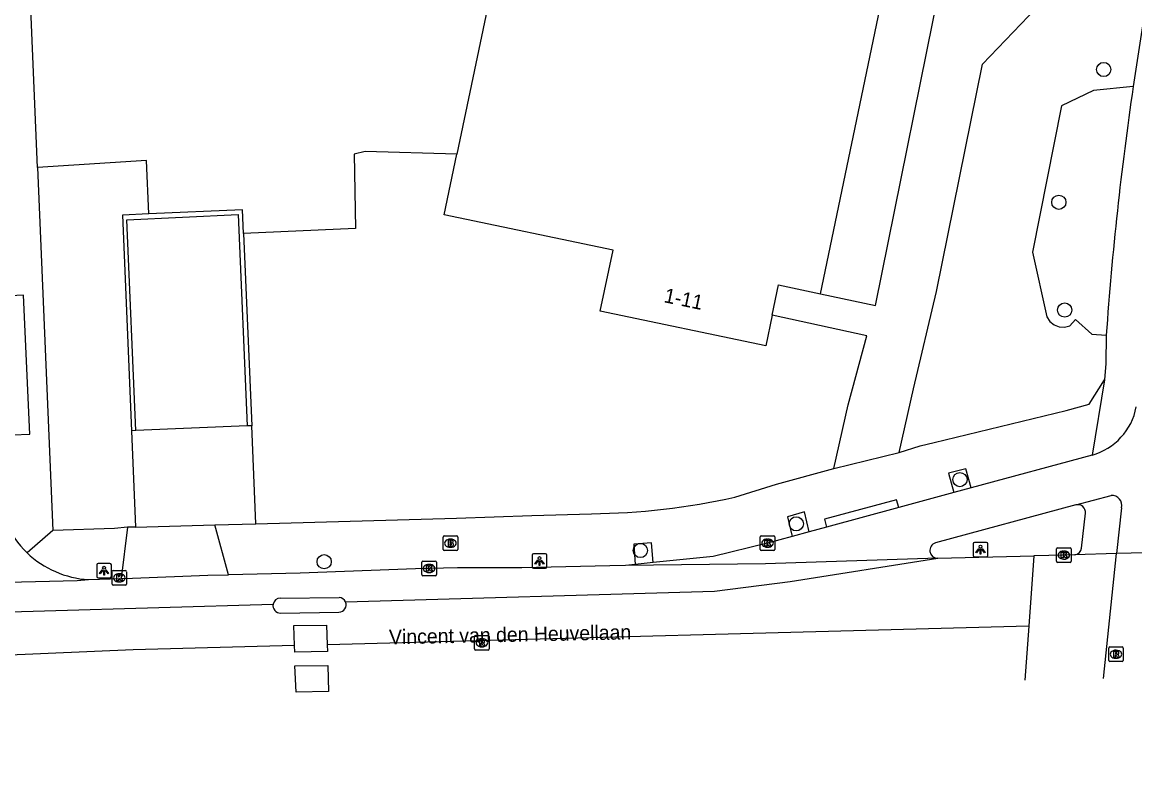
# Model space of a CAD drawing. Extents: x 161243 to 161752, y 384138 to 384885.
# Drawn here: x 161384.5 to 161461, y 384140.9 to 384193.1 of the extents above; entities that cross this region are included whole.
import ezdxf

# ---------------------------------------------------------------- set-up
doc = ezdxf.new("R2010")
doc.units = 0
for name, color, linetype in [('IMGEO_Boom', 7, 'Continuous'), ('IMGEO_Brandkraan', 7, 'Continuous'), ('IMGEO_Fietspad_gesloten', 7, 'Continuous'), ('IMGEO_Groenvoorziening', 7, 'Continuous'), ('IMGEO_Kolk', 7, 'Continuous'), ('IMGEO_Lichtpunt', 7, 'Continuous'), ('IMGEO_Muur', 7, 'Continuous'), ('IMGEO_Openbare_ruimte_label', 7, 'Continuous'), ('IMGEO_Pand', 7, 'Continuous'), ('IMGEO_Pand_nummerreeks', 7, 'Continuous'), ('IMGEO_Rijbaan_lokaal_gesloten', 7, 'Continuous'), ('IMGEO_Rijbaan_lokaal_open', 7, 'Continuous'), ('IMGEO_Rioolput', 7, 'Continuous'), ('IMGEO_Voetpad_open', 7, 'Continuous')]:
    doc.layers.add(name, color=color, linetype=linetype)

msp = doc.modelspace()

# ---------------------------------------------------------------- linework, layer by layer
at = {"layer": 'IMGEO_Boom'}
for centre in [(161458.886, 384189.809), (161455.802, 384180.674), (161456.202, 384173.26), (161448.996, 384161.6), (161437.743, 384158.555), (161427.028, 384156.723), (161405.286, 384155.947)]:
    msp.add_circle(centre, 0.489, dxfattribs=at)
at = {"layer": 'IMGEO_Brandkraan'}
for p, q in [((161413.464, 384156.795), (161413.464, 384157.647)), ((161413.539, 384157.721), (161414.391, 384157.721)), ((161414.465, 384157.647), (161414.465, 384156.795)), ((161413.975, 384156.941), (161413.95, 384156.941)), ((161413.952, 384157.501), (161413.977, 384157.501)), ((161414.391, 384156.721), (161413.539, 384156.721))]:
    msp.add_line(p, q, dxfattribs=at)
for points in [[(161413.464, 384156.795), (161413.464, 384157.647)], [(161413.539, 384157.721), (161414.391, 384157.721)], [(161414.465, 384157.647), (161414.465, 384156.795)], [(161413.812, 384157.421), (161413.812, 384157.021), (161414.025, 384157.021)], [(161414.043, 384157.421), (161413.812, 384157.421)], [(161413.991, 384157.34), (161413.937, 384157.34), (161413.937, 384157.264)], [(161413.937, 384157.264), (161413.99, 384157.264)], [(161413.999, 384157.188), (161413.937, 384157.188), (161413.937, 384157.107)], [(161413.937, 384157.107), (161413.999, 384157.107)], [(161414.391, 384156.721), (161413.539, 384156.721)]]:
    msp.add_lwpolyline(points, dxfattribs=at)
for centre, radius, start, end in [((161413.541, 384157.645), 0.0765, 91.55205, 178.44795), ((161413.541, 384157.645), 0.0765, 91.55205, 178.44795), ((161414.389, 384157.645), 0.0765, 1.55205, 88.44795), ((161414.389, 384157.645), 0.0765, 1.55205, 88.44795), ((161413.992, 384157.302), 0.0379, 267.82845, 90.93552), ((161414, 384157.147), 0.0404, 269.87594, 90.50774), ((161414.031, 384157.272), 0.251, 268.66757, 293.53466), ((161414.047, 384157.276), 0.145, 59.4692, 91.53667), ((161414.072, 384157.323), 0.0922, 285.51372, 58.15012), ((161414.077, 384157.131), 0.105, 301.31148, 78.98903), ((161413.541, 384156.797), 0.0765, 181.55205, 268.44795), ((161413.541, 384156.797), 0.0765, 181.55205, 268.44795), ((161414.389, 384156.797), 0.0765, 271.55205, 358.44795), ((161414.389, 384156.797), 0.0765, 271.55205, 358.44795)]:
    msp.add_arc(centre, radius, start, end, dxfattribs=at)
for centre, major_axis, ratio, start_param, end_param in [((161413.951, 384157.221), (-0.387, 0.002), 0.722429, 4.712389, 7.853982), ((161413.976, 384157.221), (-0.39, 0.002), 0.717154, 1.570796, 4.712389)]:
    msp.add_ellipse(centre, major_axis=major_axis, ratio=ratio, start_param=start_param, end_param=end_param, dxfattribs=at)
at = {"layer": 'IMGEO_Fietspad_gesloten'}
for points in [[(161458.084, 384163.277), (161449.764, 384161.023)], [(161448.578, 384160.702), (161444.788, 384159.674)], [(161449.764, 384161.023), (161448.578, 384160.702)], [(161456.979, 384159.857), (161459.397, 384160.506)], [(161444.788, 384159.674), (161439.834, 384158.33)], [(161456.979, 384159.857), (161447.315, 384157.238)], [(161460.109, 384159.665), (161459.765, 384156.516)], [(161437.465, 384157.687), (161435.768, 384157.227), (161432.032, 384156.309), (161427.896, 384155.889)], [(161438.642, 384158.007), (161437.465, 384157.687)], [(161439.834, 384158.33), (161438.642, 384158.007)], [(161462.762, 384156.587), (161459.765, 384156.516)], [(161426.672, 384155.766), (161425.997, 384155.697)], [(161427.896, 384155.889), (161426.672, 384155.766)]]:
    msp.add_lwpolyline(points, dxfattribs=at)
for centre, radius, start, end in [((161456.898, 384167.418), 4.308, 285.98546, 348.96705), ((161459.435, 384159.816), 0.691, 347.33285, 93.1704), ((161447.472, 384156.724), 0.538, 106.93515, 270.57355)]:
    msp.add_arc(centre, radius, start, end, dxfattribs=at)
at = {"layer": 'IMGEO_Groenvoorziening'}
for points in [[(161460.912, 384188.629), (161458.176, 384188.358), (161455.984, 384187.299), (161453.993, 384177.235), (161454.985, 384172.801), (161455.184, 384172.482), (161455.473, 384172.241), (161455.823, 384172.102), (161456.199, 384172.08), (161456.563, 384172.177), (161456.942, 384172.609), (161458.066, 384171.601), (161459.056, 384171.523)], [(161414.411, 384183.984), (161408.1, 384184.171), (161407.337, 384183.973), (161407.43, 384178.871), (161399.739, 384178.529)], [(161393.229, 384179.87), (161393.06, 384183.551), (161385.58, 384183.057)]]:
    msp.add_lwpolyline(points, dxfattribs=at)
at = {"layer": 'IMGEO_Kolk'}
for p, q in [((161435.267, 384156.801), (161435.267, 384157.653)), ((161435.342, 384157.727), (161436.194, 384157.727)), ((161436.268, 384157.653), (161436.268, 384156.801)), ((161435.778, 384156.947), (161435.753, 384156.947)), ((161435.755, 384157.507), (161435.78, 384157.507)), ((161455.642, 384155.98), (161455.642, 384156.832)), ((161455.717, 384156.906), (161456.569, 384156.906)), ((161456.643, 384156.832), (161456.643, 384155.98)), ((161436.194, 384156.727), (161435.342, 384156.727)), ((161456.153, 384156.126), (161456.128, 384156.126)), ((161456.13, 384156.686), (161456.155, 384156.686)), ((161390.777, 384155.339), (161391.629, 384155.339)), ((161411.997, 384155.062), (161411.997, 384155.914)), ((161412.072, 384155.988), (161412.924, 384155.988)), ((161412.485, 384155.768), (161412.51, 384155.768)), ((161412.998, 384155.914), (161412.998, 384155.062)), ((161456.569, 384155.906), (161455.717, 384155.906)), ((161390.702, 384154.413), (161390.702, 384155.265)), ((161391.213, 384154.559), (161391.188, 384154.559)), ((161391.19, 384155.119), (161391.215, 384155.119)), ((161391.703, 384155.265), (161391.703, 384154.413)), ((161412.924, 384154.988), (161412.072, 384154.988)), ((161412.508, 384155.208), (161412.483, 384155.208)), ((161391.629, 384154.339), (161390.777, 384154.339))]:
    msp.add_line(p, q, dxfattribs=at)
for points in [[(161435.267, 384156.801), (161435.267, 384157.653)], [(161435.342, 384157.727), (161436.194, 384157.727)], [(161436.268, 384157.653), (161436.268, 384156.801)], [(161435.588, 384157.427), (161435.711, 384157.427), (161435.711, 384157.276), (161435.841, 384157.427), (161436.005, 384157.427), (161435.859, 384157.276), (161436.012, 384157.027), (161435.86, 384157.027), (161435.775, 384157.191), (161435.711, 384157.124), (161435.711, 384157.027), (161435.588, 384157.027), (161435.588, 384157.427)], [(161455.642, 384155.98), (161455.642, 384156.832)], [(161455.717, 384156.906), (161456.569, 384156.906)], [(161456.643, 384156.832), (161456.643, 384155.98)], [(161436.194, 384156.727), (161435.342, 384156.727)], [(161455.963, 384156.606), (161456.086, 384156.606), (161456.086, 384156.455), (161456.216, 384156.606), (161456.38, 384156.606), (161456.234, 384156.455), (161456.387, 384156.206), (161456.235, 384156.206), (161456.15, 384156.37), (161456.086, 384156.303), (161456.086, 384156.206), (161455.963, 384156.206), (161455.963, 384156.606)], [(161390.777, 384155.339), (161391.629, 384155.339)], [(161411.997, 384155.062), (161411.997, 384155.914)], [(161412.072, 384155.988), (161412.924, 384155.988)], [(161412.318, 384155.688), (161412.441, 384155.688), (161412.441, 384155.537), (161412.571, 384155.688), (161412.735, 384155.688), (161412.589, 384155.537), (161412.742, 384155.288), (161412.59, 384155.288), (161412.505, 384155.452), (161412.441, 384155.385), (161412.441, 384155.288), (161412.318, 384155.288), (161412.318, 384155.688)], [(161412.998, 384155.914), (161412.998, 384155.062)], [(161456.569, 384155.906), (161455.717, 384155.906)], [(161390.702, 384154.413), (161390.702, 384155.265)], [(161391.023, 384155.039), (161391.146, 384155.039), (161391.146, 384154.888), (161391.276, 384155.039), (161391.44, 384155.039), (161391.294, 384154.888), (161391.447, 384154.639), (161391.295, 384154.639), (161391.21, 384154.803), (161391.146, 384154.736), (161391.146, 384154.639), (161391.023, 384154.639), (161391.023, 384155.039)], [(161391.703, 384155.265), (161391.703, 384154.413)], [(161412.924, 384154.988), (161412.072, 384154.988)], [(161391.629, 384154.339), (161390.777, 384154.339)]]:
    msp.add_lwpolyline(points, dxfattribs=at)
for centre, start, end in [((161435.344, 384157.651), 91.55205, 178.44795), ((161435.344, 384157.651), 91.55205, 178.44795), ((161436.192, 384157.651), 1.55205, 88.44795), ((161436.192, 384157.651), 1.55205, 88.44795), ((161455.719, 384156.83), 91.55205, 178.44795), ((161455.719, 384156.83), 91.55205, 178.44795), ((161456.567, 384156.83), 1.55205, 88.44795), ((161456.567, 384156.83), 1.55205, 88.44795), ((161435.344, 384156.803), 181.55205, 268.44795), ((161435.344, 384156.803), 181.55205, 268.44795), ((161436.192, 384156.803), 271.55205, 358.44795), ((161436.192, 384156.803), 271.55205, 358.44795), ((161390.779, 384155.263), 91.55205, 178.44795), ((161390.779, 384155.263), 91.55205, 178.44795), ((161391.627, 384155.263), 1.55205, 88.44795), ((161391.627, 384155.263), 1.55205, 88.44795), ((161412.074, 384155.912), 91.55205, 178.44795), ((161412.074, 384155.912), 91.55205, 178.44795), ((161412.922, 384155.912), 1.55205, 88.44795), ((161412.922, 384155.912), 1.55205, 88.44795), ((161455.719, 384155.982), 181.55205, 268.44795), ((161455.719, 384155.982), 181.55205, 268.44795), ((161456.567, 384155.982), 271.55205, 358.44795), ((161456.567, 384155.982), 271.55205, 358.44795), ((161412.074, 384155.064), 181.55205, 268.44795), ((161412.074, 384155.064), 181.55205, 268.44795), ((161412.922, 384155.064), 271.55205, 358.44795), ((161412.922, 384155.064), 271.55205, 358.44795), ((161390.779, 384154.415), 181.55205, 268.44795), ((161390.779, 384154.415), 181.55205, 268.44795), ((161391.627, 384154.415), 271.55205, 358.44795), ((161391.627, 384154.415), 271.55205, 358.44795)]:
    msp.add_arc(centre, 0.0765, start, end, dxfattribs=at)
for centre, major_axis, ratio, start_param, end_param in [((161435.754, 384157.227), (-0.387, 0.002), 0.722429, 4.712389, 7.853982), ((161435.779, 384157.227), (-0.39, 0.002), 0.717154, 1.570796, 4.712389), ((161456.129, 384156.406), (-0.387, 0.002), 0.722429, 4.712389, 7.853982), ((161456.154, 384156.406), (-0.39, 0.002), 0.717154, 1.570796, 4.712389), ((161412.484, 384155.488), (-0.387, 0.002), 0.722429, 4.712389, 7.853982), ((161412.509, 384155.488), (-0.39, 0.002), 0.717154, 1.570796, 4.712389), ((161391.189, 384154.839), (-0.387, 0.002), 0.722429, 4.712389, 7.853982), ((161391.214, 384154.839), (-0.39, 0.002), 0.717154, 1.570796, 4.712389)]:
    msp.add_ellipse(centre, major_axis=major_axis, ratio=ratio, start_param=start_param, end_param=end_param, dxfattribs=at)
at = {"layer": 'IMGEO_Lichtpunt'}
for p, q in [((161449.915, 384157.186), (161449.915, 384156.379)), ((161449.915, 384157.186), (161449.915, 384156.379)), ((161450.817, 384157.281), (161450.009, 384157.281)), ((161450.817, 384157.281), (161450.009, 384157.281)), ((161450.911, 384156.379), (161450.911, 384157.186)), ((161450.911, 384156.379), (161450.911, 384157.186)), ((161419.593, 384156.404), (161419.593, 384155.597)), ((161419.593, 384156.404), (161419.593, 384155.597)), ((161420.495, 384156.499), (161419.687, 384156.499)), ((161420.495, 384156.499), (161419.687, 384156.499)), ((161420.589, 384155.597), (161420.589, 384156.404)), ((161420.589, 384155.597), (161420.589, 384156.404)), ((161450.009, 384156.285), (161450.817, 384156.285)), ((161450.009, 384156.285), (161450.817, 384156.285)), ((161389.656, 384155.736), (161389.656, 384154.929)), ((161389.656, 384155.736), (161389.656, 384154.929)), ((161390.558, 384155.831), (161389.75, 384155.831)), ((161390.558, 384155.831), (161389.75, 384155.831)), ((161390.652, 384154.929), (161390.652, 384155.736)), ((161390.652, 384154.929), (161390.652, 384155.736)), ((161419.687, 384155.503), (161420.495, 384155.503)), ((161419.687, 384155.503), (161420.495, 384155.503)), ((161389.75, 384154.835), (161390.558, 384154.835)), ((161389.75, 384154.835), (161390.558, 384154.835))]:
    msp.add_line(p, q, dxfattribs=at)
for points in [[(161450.289, 384156.85), (161450.328, 384156.822), (161450.14, 384156.56), (161450.102, 384156.587), (161450.289, 384156.85)], [(161450.501, 384156.822), (161450.539, 384156.849), (161450.726, 384156.587), (161450.687, 384156.559), (161450.501, 384156.822)], [(161419.967, 384156.068), (161420.006, 384156.04), (161419.818, 384155.778), (161419.78, 384155.805), (161419.967, 384156.068)], [(161420.179, 384156.04), (161420.217, 384156.067), (161420.404, 384155.805), (161420.365, 384155.777), (161420.179, 384156.04)], [(161450.391, 384156.802), (161450.438, 384156.802), (161450.438, 384156.48), (161450.391, 384156.48), (161450.391, 384156.802)], [(161390.03, 384155.4), (161390.069, 384155.372), (161389.881, 384155.11), (161389.843, 384155.137), (161390.03, 384155.4)], [(161390.132, 384155.352), (161390.179, 384155.352), (161390.179, 384155.03), (161390.132, 384155.03), (161390.132, 384155.352)], [(161390.242, 384155.372), (161390.28, 384155.399), (161390.467, 384155.137), (161390.428, 384155.109), (161390.242, 384155.372)], [(161420.069, 384156.02), (161420.116, 384156.02), (161420.116, 384155.698), (161420.069, 384155.698), (161420.069, 384156.02)]]:
    msp.add_lwpolyline(points, dxfattribs=at)
for centre in [(161450.414, 384156.984), (161420.092, 384156.202), (161390.155, 384155.534)]:
    msp.add_circle(centre, 0.0994, dxfattribs=at)
for centre, start, end in [((161450.009, 384157.186), 90, 180), ((161450.009, 384157.186), 90, 180), ((161450.817, 384157.186), 0, 90), ((161450.817, 384157.186), 0, 90), ((161419.687, 384156.404), 90, 180), ((161419.687, 384156.404), 90, 180), ((161420.495, 384156.404), 0, 90), ((161420.495, 384156.404), 0, 90), ((161450.009, 384156.379), 180, 270), ((161450.009, 384156.379), 180, 270), ((161450.817, 384156.379), 270, 0), ((161450.817, 384156.379), 270, 360), ((161389.75, 384155.736), 90, 180), ((161389.75, 384155.736), 90, 180), ((161390.558, 384155.736), 0, 90), ((161390.558, 384155.736), 0, 90), ((161419.687, 384155.597), 180, 270), ((161419.687, 384155.597), 180, 270), ((161420.495, 384155.597), 270, 0), ((161420.495, 384155.597), 270, 360), ((161389.75, 384154.929), 180, 270), ((161389.75, 384154.929), 180, 270), ((161390.558, 384154.929), 270, 0), ((161390.558, 384154.929), 270, 360)]:
    msp.add_arc(centre, 0.0946, start, end, dxfattribs=at)
at = {"layer": 'IMGEO_Muur'}
for points in [[(161393.229, 384179.87), (161391.41, 384179.791), (161392.037, 384164.964)], [(161392.337, 384164.977), (161391.717, 384179.474), (161399.383, 384179.831), (161400.002, 384165.294)], [(161399.739, 384178.529), (161399.67, 384180.152), (161393.229, 384179.87)], [(161399.739, 384178.529), (161400.302, 384165.307)], [(161400.302, 384165.307), (161400.002, 384165.294)], [(161392.337, 384164.977), (161392.037, 384164.964)]]:
    msp.add_lwpolyline(points, dxfattribs=at)
at = {"layer": 'IMGEO_Pand'}
for points in [[(161439.412, 384174.382), (161443.732, 384195.077), (161444.116, 384194.997), (161444.215, 384195.469), (161443.954, 384195.524), (161450.857, 384228.917)], [(161415.583, 384200.253), (161414.471, 384194.926), (161416.602, 384194.481), (161414.411, 384183.984)], [(161436.086, 384172.902), (161435.648, 384170.803), (161424.271, 384173.178), (161425.148, 384177.381), (161413.538, 384179.804), (161414.411, 384183.984)], [(161436.086, 384172.902), (161436.521, 384174.985), (161439.412, 384174.382)]]:
    msp.add_lwpolyline(points, dxfattribs=at)
at = {"layer": 'IMGEO_Rijbaan_lokaal_gesloten'}
for points in [[(161400.002, 384165.294), (161392.337, 384164.977)], [(161406.755, 384153.182), (161432.134, 384153.933), (161437.318, 384154.582), (161447.477, 384156.186)], [(161447.477, 384156.186), (161435.621, 384155.795), (161425.997, 384155.697)], [(161447.477, 384156.186), (161454.085, 384156.354)], [(161454.085, 384156.354), (161453.737, 384151.519)], [(161456.899, 384156.43), (161456.143, 384156.406), (161454.085, 384156.354)], [(161459.765, 384156.516), (161456.899, 384156.43)], [(161458.867, 384147.921), (161459.765, 384156.516)], [(161425.997, 384155.697), (161424.925, 384155.676), (161418.887, 384155.534), (161414.448, 384155.534), (161411.559, 384155.465), (161403.634, 384155.167), (161398.71, 384155.049)], [(161371.088, 384154.255), (161388.306, 384154.657), (161389.077, 384154.72)], [(161389.077, 384154.72), (161391.334, 384154.79)], [(161391.334, 384154.79), (161392.098, 384154.814), (161397.291, 384155.015), (161398.71, 384155.049)], [(161334.833, 384149.765), (161370.321, 384152.118), (161401.777, 384153.037)], [(161402.26, 384153.444), (161406.312, 384153.498)], [(161402.294, 384152.419), (161406.304, 384152.476)], [(161453.737, 384151.519), (161405.491, 384150.24)], [(161453.737, 384151.519), (161453.468, 384147.793)], [(161403.252, 384150.18), (161392.155, 384149.886), (161376.721, 384149.233), (161369.626, 384148.76), (161361.232, 384148.2), (161341.125, 384146.731), (161314.989, 384144.831), (161288.79, 384142.926), (161262, 384140.882)]]:
    msp.add_lwpolyline(points, dxfattribs=at)
for centre, radius, start, end in [((161402.277, 384152.93), 0.512, 167.96336, 271.86629), ((161402.277, 384152.933), 0.511, 91.94396, 168.29437), ((161406.281, 384152.987), 0.512, 272.52131, 22.33698), ((161406.283, 384152.988), 0.511, 22.30129, 86.69679)]:
    msp.add_arc(centre, radius, start, end, dxfattribs=at)
at = {"layer": 'IMGEO_Rijbaan_lokaal_open'}
for points in [[(161439.412, 384174.382), (161443.202, 384173.582), (161448.035, 384197.539)], [(161444.823, 384163.456), (161445.81, 384167.846), (161447.397, 384174.537), (161450.553, 384190.18), (161454.769, 384194.574)], [(161440.318, 384162.357), (161441.305, 384166.747), (161442.601, 384171.491), (161436.086, 384172.902)], [(161400.589, 384158.56), (161400.302, 384165.307)], [(161392.037, 384164.964), (161392.317, 384158.336)], [(161440.318, 384162.357), (161444.823, 384163.456)], [(161392.317, 384158.336), (161397.762, 384158.484)], [(161397.762, 384158.484), (161400.589, 384158.56)], [(161403.252, 384150.18), (161403.202, 384151.552), (161405.439, 384151.575), (161405.491, 384150.24)], [(161405.491, 384150.24), (161405.509, 384149.782), (161403.269, 384149.72), (161403.252, 384150.18)], [(161403.279, 384148.788), (161405.534, 384148.816), (161405.591, 384147.013), (161403.355, 384146.98), (161403.279, 384148.788)]]:
    msp.add_lwpolyline(points, dxfattribs=at)
for centre, radius, start, end in [((161389.463, 384161.36), 6.648, 181.57978, 226.19767), ((161389.469, 384161.364), 6.655, 226.17773, 266.62056)]:
    msp.add_arc(centre, radius, start, end, dxfattribs=at)
at = {"layer": 'IMGEO_Rioolput'}
for p, q in [((161415.627, 384149.948), (161415.627, 384150.8)), ((161415.702, 384150.874), (161416.554, 384150.874)), ((161416.628, 384150.8), (161416.628, 384149.948)), ((161416.138, 384150.094), (161416.113, 384150.094)), ((161416.115, 384150.654), (161416.14, 384150.654)), ((161459.229, 384149.158), (161459.229, 384150.01)), ((161459.304, 384150.084), (161460.156, 384150.084)), ((161460.23, 384150.01), (161460.23, 384149.158)), ((161416.554, 384149.874), (161415.702, 384149.874)), ((161459.74, 384149.304), (161459.715, 384149.304)), ((161459.717, 384149.864), (161459.742, 384149.864)), ((161460.156, 384149.084), (161459.304, 384149.084))]:
    msp.add_line(p, q, dxfattribs=at)
for points in [[(161415.627, 384149.948), (161415.627, 384150.8)], [(161415.702, 384150.874), (161416.554, 384150.874)], [(161416.628, 384150.8), (161416.628, 384149.948)], [(161416.216, 384150.572), (161415.964, 384150.574), (161415.964, 384150.174)], [(161415.964, 384150.174), (161416.088, 384150.174), (161416.088, 384150.336), (161416.099, 384150.336)], [(161416.142, 384150.493), (161416.088, 384150.493), (161416.088, 384150.412)], [(161416.088, 384150.412), (161416.14, 384150.412)], [(161416.146, 384150.307), (161416.217, 384150.174), (161416.357, 384150.174), (161416.292, 384150.3)], [(161459.229, 384149.158), (161459.229, 384150.01)], [(161459.304, 384150.084), (161460.156, 384150.084)], [(161460.23, 384150.01), (161460.23, 384149.158)], [(161416.554, 384149.874), (161415.702, 384149.874)], [(161459.818, 384149.782), (161459.566, 384149.784), (161459.566, 384149.384)], [(161459.566, 384149.384), (161459.69, 384149.384), (161459.69, 384149.546), (161459.701, 384149.546)], [(161459.744, 384149.703), (161459.69, 384149.703), (161459.69, 384149.622)], [(161459.69, 384149.622), (161459.742, 384149.622)], [(161459.748, 384149.517), (161459.819, 384149.384), (161459.959, 384149.384), (161459.894, 384149.51)], [(161460.156, 384149.084), (161459.304, 384149.084)]]:
    msp.add_lwpolyline(points, dxfattribs=at)
for centre, radius, start, end in [((161415.704, 384150.798), 0.0765, 91.55205, 178.44795), ((161415.704, 384150.798), 0.0765, 91.55205, 178.44795), ((161416.552, 384150.798), 0.0765, 1.55205, 88.44795), ((161416.552, 384150.798), 0.0765, 1.55205, 88.44795), ((161415.704, 384149.95), 0.0765, 181.55205, 268.44795), ((161415.704, 384149.95), 0.0765, 181.55205, 268.44795), ((161416.098, 384150.283), 0.0533, 26.02933, 88.69889), ((161416.124, 384150.601), 0.19, 274.7715, 282.96867), ((161416.148, 384150.397), 0.0964, 77.00612, 93.18647), ((161416.162, 384150.454), 0.0378, 276.66336, 79.67722), ((161416.215, 384150.462), 0.109, 350.36119, 89.41601), ((161416.213, 384150.462), 0.112, 277.58423, 350.98172), ((161416.197, 384150.247), 0.108, 29.51342, 73.79051), ((161416.552, 384149.95), 0.0765, 271.55205, 358.44795), ((161416.552, 384149.95), 0.0765, 271.55205, 358.44795), ((161459.306, 384150.008), 0.0765, 91.55205, 178.44795), ((161459.306, 384150.008), 0.0765, 91.55205, 178.44795), ((161460.154, 384150.008), 0.0765, 1.55205, 88.44795), ((161460.154, 384150.008), 0.0765, 1.55205, 88.44795), ((161459.7, 384149.493), 0.0533, 26.02933, 88.69889), ((161459.726, 384149.811), 0.19, 274.7715, 282.96867), ((161459.75, 384149.607), 0.0964, 77.00612, 93.18647), ((161459.764, 384149.664), 0.0378, 276.66336, 79.67722), ((161459.817, 384149.672), 0.109, 350.36119, 89.41601), ((161459.815, 384149.672), 0.112, 277.58423, 350.98172), ((161459.799, 384149.457), 0.108, 29.51342, 73.79051), ((161459.306, 384149.16), 0.0765, 181.55205, 268.44795), ((161459.306, 384149.16), 0.0765, 181.55205, 268.44795), ((161460.154, 384149.16), 0.0765, 271.55205, 358.44795), ((161460.154, 384149.16), 0.0765, 271.55205, 358.44795)]:
    msp.add_arc(centre, radius, start, end, dxfattribs=at)
for centre, major_axis, ratio, start_param, end_param in [((161416.114, 384150.374), (-0.387, 0.002), 0.722429, 4.712389, 7.853982), ((161416.139, 384150.374), (-0.39, 0.002), 0.717154, 1.570796, 4.712389), ((161459.716, 384149.584), (-0.387, 0.002), 0.722429, 4.712389, 7.853982), ((161459.741, 384149.584), (-0.39, 0.002), 0.717154, 1.570796, 4.712389)]:
    msp.add_ellipse(centre, major_axis=major_axis, ratio=ratio, start_param=start_param, end_param=end_param, dxfattribs=at)
at = {"layer": 'IMGEO_Voetpad_open'}
for points in [[(161385.58, 384183.057), (161384.168, 384216.383), (161381.889, 384271.203), (161381.629, 384276.193), (161382.268, 384292.057), (161382.629, 384295.041)], [(161468.323, 384228.48), (161468.282, 384228.265), (161466.465, 384219.382), (161466.186, 384217.884), (161464.994, 384211.701), (161464.952, 384211.554), (161463.869, 384205.765), (161463.831, 384205.598), (161462.81, 384199.882), (161462.766, 384199.717), (161461.588, 384193.018), (161461.56, 384192.809), (161460.912, 384188.629)], [(161385.58, 384183.057), (161386.637, 384158.099)], [(161382.693, 384164.623), (161385.038, 384164.73), (161384.605, 384174.293), (161382.333, 384174.169)], [(161459.056, 384171.523), (161459.042, 384169.59), (161458.949, 384168.46)], [(161444.823, 384163.456), (161446.255, 384163.919), (161447.23, 384164.158), (161456.3, 384166.349), (161457.892, 384166.781), (161458.949, 384168.46)], [(161458.949, 384168.46), (161458.084, 384163.277)], [(161433.522, 384160.391), (161436.394, 384161.282), (161440.318, 384162.357)], [(161449.764, 384161.023), (161449.411, 384162.348), (161448.223, 384162.035), (161448.578, 384160.702)], [(161444.788, 384159.674), (161444.643, 384160.214), (161439.685, 384158.886), (161439.834, 384158.33)], [(161400.589, 384158.56), (161414.377, 384158.936), (161419.572, 384159.122), (161423.657, 384159.253)], [(161438.642, 384158.007), (161438.312, 384159.38), (161437.14, 384159.04), (161437.465, 384157.687)], [(161457.361, 384156.891), (161457.625, 384159.28)], [(161398.71, 384155.049), (161397.762, 384158.484)], [(161386.637, 384158.099), (161384.861, 384156.562)], [(161391.76, 384158.321), (161390.867, 384158.244), (161386.637, 384158.099)], [(161391.76, 384158.321), (161391.334, 384154.79)], [(161392.317, 384158.336), (161391.76, 384158.321)], [(161427.896, 384155.889), (161427.801, 384157.237), (161426.576, 384157.152), (161426.672, 384155.766)]]:
    msp.add_lwpolyline(points, dxfattribs=at)
for centre, radius, start, end in [((161689.987, 384155.121), 231.513, 171.67799, 175.93728), ((161423.309, 384205.596), 46.344, 270.43003, 282.73077), ((161457.109, 384159.352), 0.521, 352.0439, 104.41435), ((161456.848, 384156.943), 0.515, 275.64991, 354.22594)]:
    msp.add_arc(centre, radius, start, end, dxfattribs=at)

# ---------------------------------------------------------------- texts
at = {"layer": 'IMGEO_Openbare_ruimte_label'}
msp.add_text('Vincent van den Heuvellaan', height=1, rotation=1.20303, dxfattribs=at).set_placement((161409.756, 384150.264))
at = {"layer": 'IMGEO_Pand_nummerreeks'}
msp.add_text('1-11', height=1, rotation=348.20853, dxfattribs=at).set_placement((161428.594, 384173.808))

doc.saveas('drawing.dxf')
